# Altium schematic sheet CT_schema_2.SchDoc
size 386 x 209 mm
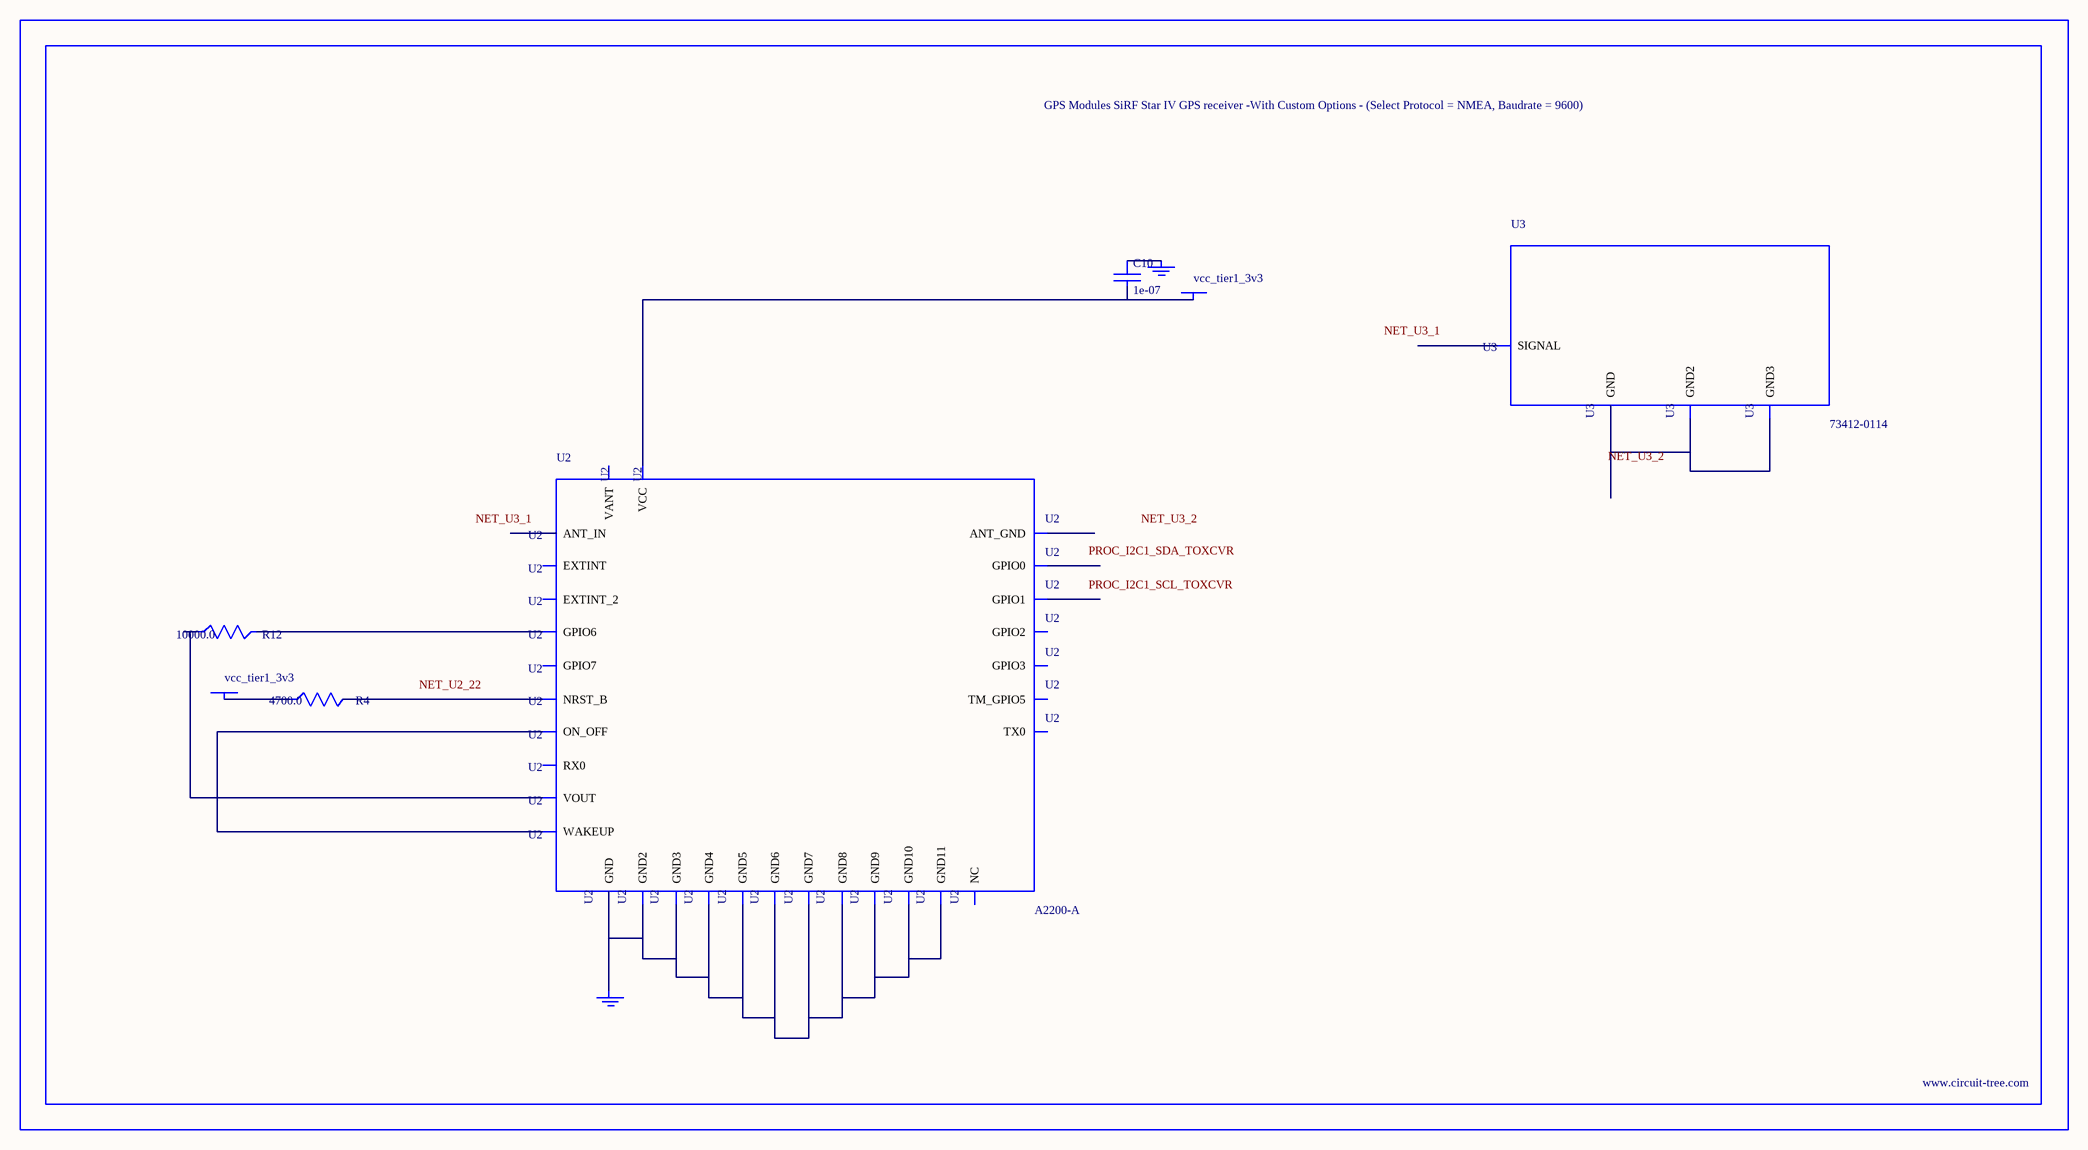
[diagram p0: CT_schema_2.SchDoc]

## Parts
BORDER1  (no value)
C10  1e-07  [C0402]
GND_INSTANCE_1_0  (no value)
GND_INSTANCE_1_1  (no value)
POWER_INSTANCE_1_0  vcc_tier1_3v3
POWER_INSTANCE_1_1  vcc_tier1_3v3
R4  4700.0  [R0603]
R12  10000.0  [R0603]
U2  A2200-A  [A2200-A]
U3  73412-0114  [COAXIAL_C]

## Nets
NetC10_1: C10.1 GND_INSTANCE_1_0.0(GND)
NetC10_2: C10.2 POWER_INSTANCE_1_0.0(PWR) U2.20(VCC)
NetGND_INSTANCE_1_1_0: GND_INSTANCE_1_1.0(GND) U2.7(GND) U2.8(GND2) U2.23(GND3) U2.24(GND4) U2.25(GND5) U2.26(GND6) U2.27(GND7) U2.28(GND8) U2.29(GND9) U2.30(GND10) U2.31(GND11)
NetPOWER_INSTANCE_1_1_0: POWER_INSTANCE_1_1.0(PWR) R4.1
NetR4_2: R4.2 U2.22(NRST_B)
NetR12_1: R12.1 U2.2(VOUT)
NetR12_2: R12.2 U2.17(GPIO6)
NetU2_6: U2.6(ON_OFF) U2.19(WAKEUP)
NetU3_2: U3.2(GND) U3.3(GND2) U3.4(GND3)

Not connected (* = marked no-connect by the designer): U2 1(GPIO2) 3(TX0) 4(RX0) 5(EXTINT_2) 9(VANT) 10(ANT_GND) 11(ANT_IN) 12(GPIO3) 13(EXTINT) 14(TM_GPIO5) 15(GPIO1) 16(GPIO0) 18(GPIO7) 21(NC); U3 1(SIGNAL)

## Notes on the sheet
- Labels drawn without touching a wire or pin: NET_U2_22, NET_U3_1, NET_U3_2, PROC_I2C1_SCL_TOXCVR, PROC_I2C1_SDA_TOXCVR

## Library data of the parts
BORDER1 = BORDER_PAGE1
C10 = C0402C104K3RACTU
GND_INSTANCE_1_0 GND_INSTANCE_1_1 = GND
POWER_INSTANCE_1_0 POWER_INSTANCE_1_1 = PWR
R4 = RC0603JR-074K7L
R12 = RC0603JR-0710KL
